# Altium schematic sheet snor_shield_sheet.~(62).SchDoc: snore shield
size A4
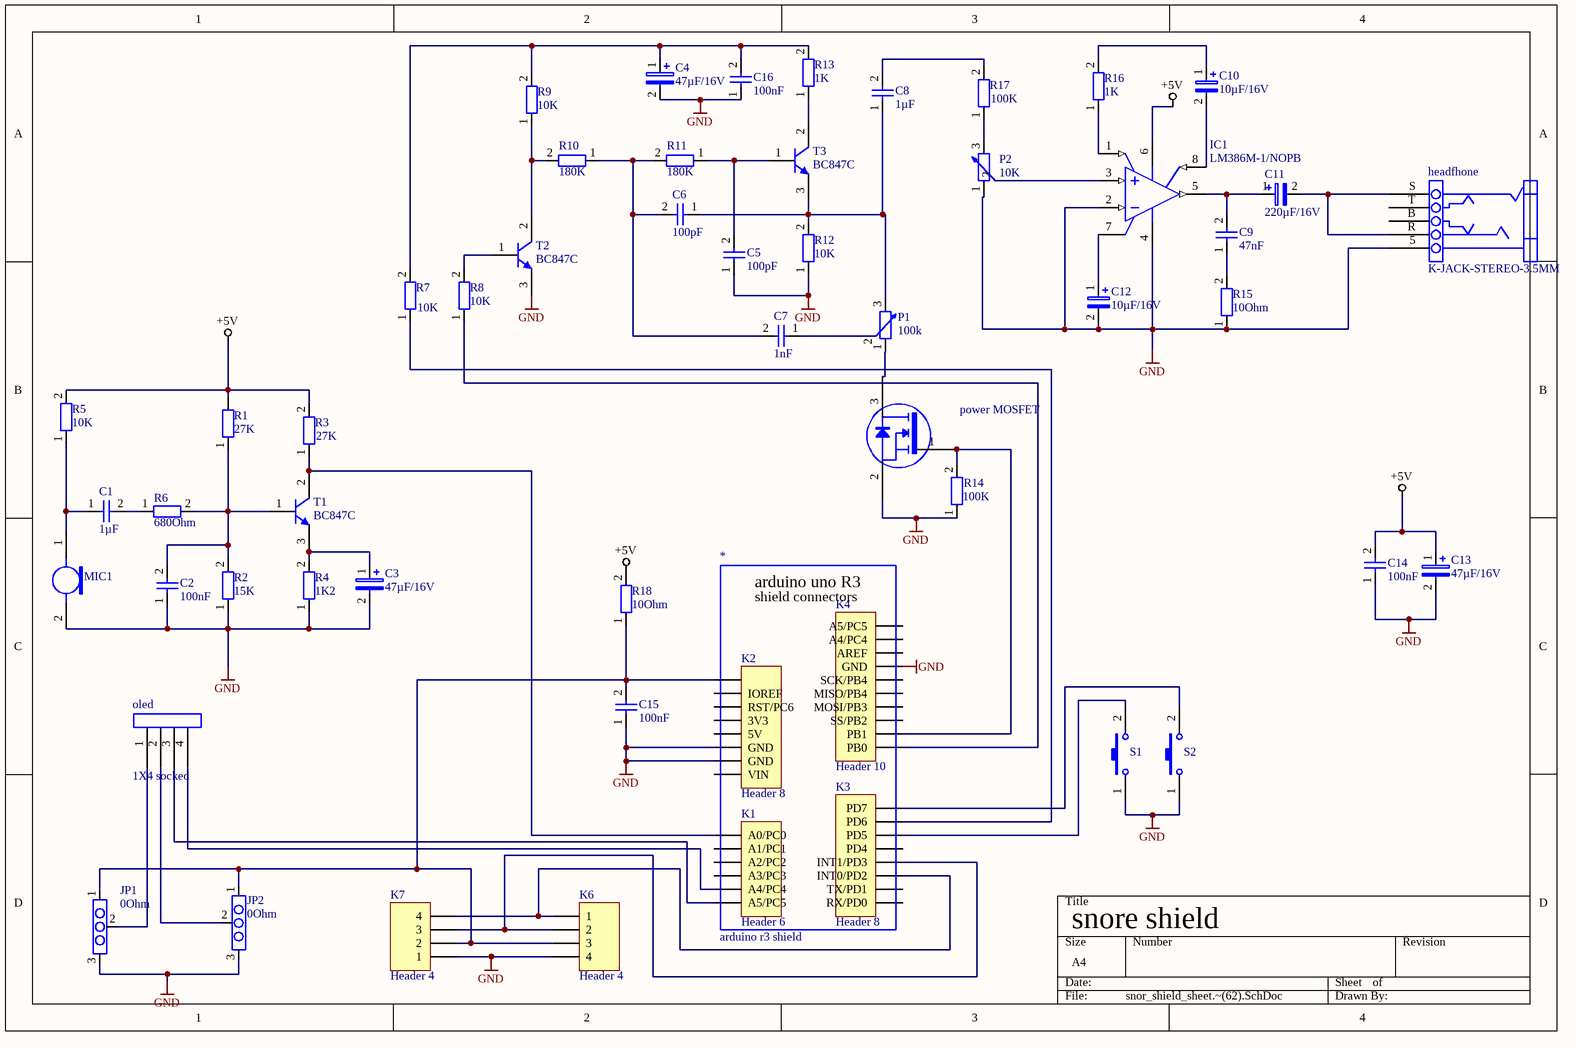
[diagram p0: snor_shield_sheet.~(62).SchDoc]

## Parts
*  arduino r3 shield
C1  value 1µF  [SMD 0805]  (hidden comment: Capitor)
C2  value 100nF  [SMD 0805]  (hidden comment: Capitor)
C3  value 47µF/16V  [elektor trans 2]  (hidden comment: Cap Pol1)
C4  value 47µF/16V  [elektor trans 2]  (hidden comment: Cap Pol1)
C5  value 100pF  [SMD 0805]  (hidden comment: Capitor)
C6  value 100pF  [SMD 0805]  (hidden comment: Capitor)
C7  value 1nF  [SMD 0805]  (hidden comment: Capitor)
C8  value 1µF  [SMD 0805]  (hidden comment: Capitor)
C9  value 47nF  [SMD 0805]  (hidden comment: Capitor)
C10  value 10µF/16V  [elecktor trans 1]  (hidden comment: Cap Pol1)
C11  value 220µF/16V  [elektor trans 3]  (hidden comment: Cap Pol1)
C12  value 10µF/16V  [elecktor trans 1]  (hidden comment: Cap Pol1)
C13  value 47µF/16V  [elektor trans 2]  (hidden comment: Cap Pol1)
C14  value 100nF  [SMD 0805]  (hidden comment: Cap)
C15  value 100nF  [SMD 0805]  (hidden comment: Capitor)
C16  value 100nF  [SMD 0805]  (hidden comment: Capitor)
headfhone  K-JACK-STEREO-3.5MM  [adioplug3.5mm]
IC1  LM386M-1/NOPB  [LM386M-1/NOPB]
JP1  value 0Ohm  [soldeer_jumper]  (hidden comment: Res2)
JP2  value 0Ohm  [soldeer_jumper]  (hidden comment: Res2)
K1  Header 6  [HDR1X6]
K2  Header 8  [HDR1X8]
K3  Header 8  [HDR1X8]
K4  Header 10  [HDR1X10]
K6  Header 4  [HDR1X4]
K7  Header 4  [HDR1X4]
MIC1  Mic2  [Electret Condenser Microphone]  (value not drawn)
mosfet  power MOSFET  [power mosfet]
oled  1X4 socked  [oled scherm]
P1  value 100k  [potmeter]  (hidden comment: Res Adj2)
P2  value 10K  [potmeter]  (hidden comment: Res Adj2)
R1  value 27K  [SMD 0805]  (hidden comment: weerstand)
R2  value 15K  [SMD 0805]  (hidden comment: weerstand)
R3  value 27K  [SMD 0805]  (hidden comment: weerstand)
R4  value 1K2  [SMD 0805]  (hidden comment: weerstand)
R5  value 10K  [SMD 0805]  (hidden comment: weerstand)
R6  value 680Ohm  [SMD 0805]  (hidden comment: weerstand)
R7  value 10K  [SMD 0805]  (hidden comment: weerstand)
R8  value 10K  [SMD 0805]  (hidden comment: weerstand)
R9  value 10K  [SMD 0805]  (hidden comment: weerstand)
R10  value 180K  [SMD 0805]  (hidden comment: weerstand)
R11  value 180K  [SMD 0805]  (hidden comment: weerstand)
R12  value 10K  [SMD 0805]  (hidden comment: weerstand)
R13  value 1K  [SMD 0805]  (hidden comment: weerstand)
R14  value 100K  [SMD 0805]  (hidden comment: weerstand)
R15  value 10Ohm  [SMD 0805]  (hidden comment: weerstand)
R16  value 1K  [SMD 0805]  (hidden comment: weerstand)
R17  value 100K  [SMD 0805]  (hidden comment: Res2)
R18  value 10Ohm  [SMD 0805]  (hidden comment: weerstand)
S1  SW-PB  [switch]  (value not drawn)
S2  SW-PB  [switch]  (value not drawn)
T1  BC847C  [bipolar BjT]
T2  BC847C  [bipolar BjT]
T3  BC847C  [bipolar BjT]

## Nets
+5V: C13.1 C14.2 IC1.6(VS) R1.2 R3.2 R5.2 R18.2
GND: C2.1 C3.2 C4.2 C5.1 C12.2 C13.2 C14.1 C15.1 C16.1 headfhone.5 IC1.2(IN-) IC1.4(GND) JP1.3 JP2.3 K2.6(GND) K2.7(GND) K4.7(GND) K6.4 K7.1 MIC1.2(uitgang) mosfet.2 P2.1 R2.1 R4.1 R12.1 R14.1 R15.1 S1.1 S2.1 T2.3(E)
NetC1_1: C1.1 MIC1.1 R5.1
NetC1_2: C1.2 R6.1
NetC2_2: C2.2 R1.1 R2.2 R6.2 T1.1(B)
NetC3_1: C3.1 R4.2 T1.3(E)
NetC4_1: C4.1 C16.2 R7.2 R9.2 R13.2
NetC5_2: C5.2 R11.1 T3.1(B)
NetC6_1: C6.1 C8.1 P1.3 R12.2 T3.3(E)
NetC6_2: C6.2 C7.2 R10.1 R11.2
NetC7_1: C7.1 P1.2
NetC8_2: C8.2 R17.2
NetC9_1: C9.1 R15.2
NetC9_2: C9.2 C11.1 IC1.5(VOUT)
NetC10_1: C10.1 R16.2
NetC10_2: C10.2 IC1.8(GAIN)
NetC11_2: C11.2 headfhone.R headfhone.S
NetC12_1: C12.1 IC1.7(BYPASS)
NetC15_2: C15.2 JP1.1 JP2.1 K2.1 K6.3 K7.2 R18.1
NetIC1_1: IC1.1(GAIN) R16.1
NetIC1_3: IC1.3(IN+) P2.2
NetJP1_2: JP1.2 oled.1
NetJP2_2: JP2.2 oled.2
NetK1_1: K1.1(A0/PC0) R3.1 T1.2(C)
NetK1_5: K1.5(A4/PC4) oled.4
NetK1_6: K1.6(A5/PC5) oled.3
NetK3_3: K3.3(INT0/PD2) K6.1 K7.4
NetK3_4: K3.4(INT1/PD3) K6.2 K7.3
NetK3_6: K3.6(PD5) S1.2
NetK3_7: K3.7(PD6) R7.1
NetK3_8: K3.8(PD7) S2.2
NetK4_1: K4.1(PB0) R8.1
NetK4_2: K4.2(PB1) mosfet.1 R14.2
Netmosfet_3: mosfet.3 P1.1
NetP2_3: P2.3 R17.1
NetR8_2: R8.2 T2.1(B)
NetR9_1: R9.1 R10.2 T2.2(C)
NetR13_1: R13.1 T3.2(C)

Not connected (* = marked no-connect by the designer): headfhone B(3) T(2); K1 2(A1/PC1) 3(A2/PC2) 4(A3/PC3); K2 2(IOREF) 3(RST/PC6) 4(3V3) 5(5V) 8(VIN); K3 1(RX/PD0) 2(TX/PD1) 5(PD4); K4 3(SS/PB2) 4(MOSI/PB3) 5(MISO/PB4) 6(SCK/PB4) 8(AREF) 9(A4/PC4) 10(A5/PC5)

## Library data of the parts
C1 C2 C5-C9 C14-C16 = Capitor: Capacitor
C3 C4 C13 = Cap Pol1_1: Polarized Capacitor (Radial) 47µF
C10 C12 = Cap Pol1: Polarized Capacitor (Radial) 10µF
C11 = Cap Pol1_2: Polarized Capacitor (Radial) 220µF
JP1 JP2 = solderjump: Resistor
K1 = Header 6: Header, 6-Pin
K2 K3 = Header 8: Header, 8-Pin
K4 = Header 10: Header, 10-Pin
K6 = Header 4: Header, 4-Pin
K7 = Header 4: Header, 4-Pin,2mm
MIC1 = Mic2: Microphone
P1 = Res Adj2: Variable Resistor 10K; Set Position: 0.5
P2 = Res Adj2_1: Variable Resistor; Set Position: 0.5
R1-R18 = weerstand: Resistor
S1 S2 = switch
T1-T3 = BJT: NPN General Purpose Amplifier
